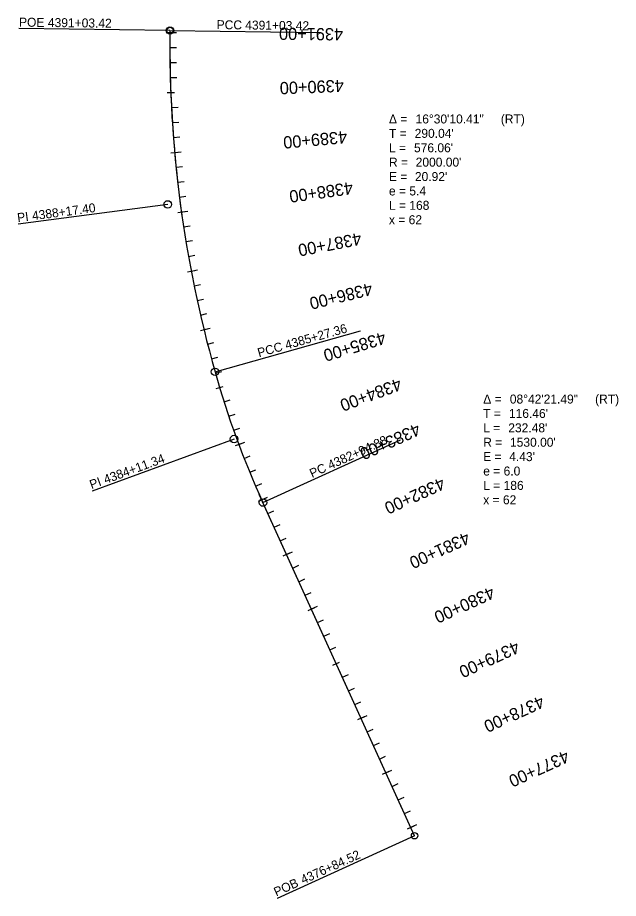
# Model space of a CAD drawing. Extents: x 20506513 to 20507516, y 7970457 to 7971925.
import ezdxf

# ---------------------------------------------------------------- set-up
doc = ezdxf.new("R2010")
doc.units = 0
for name, color, linetype in [('Alignment', 7, 'Continuous'), ('TextAlignment', 7, 'Continuous'), ('TextAlignmentLrg', 7, 'Continuous'), ('TextAlignmentSml', 7, 'Continuous')]:
    doc.layers.add(name, color=color, linetype=linetype)

msp = doc.modelspace()

# ---------------------------------------------------------------- linework, layer by layer
at = {"layer": 'Alignment'}
for q in [(20506916.7, 7971130), (20506922.8, 7971116.7)]:
    msp.add_line((20507175.7, 7970561.2), q, dxfattribs=at)
for centre, radius, start, end in [((20508767.4, 7971878.7), 2000, 179.2791, 188.1288), ((20508767.4, 7971878.7), 2000, 179.2791, 195.782), ((20508315.1, 7971750.8), 1530, 195.782, 204.4879), ((20508315.1, 7971750.8), 1530, 195.782, 204.4879)]:
    msp.add_arc(centre, radius, start, end, dxfattribs=at)
at = {"layer": 'TextAlignment'}
for p, q in [((20506767.6, 7971903.8), (20506515.6, 7971907)), ((20506515.6, 7971907), (20506515.6, 7971907)), ((20506767.6, 7971903.8), (20507019.5, 7971900.7)), ((20507019.5, 7971900.7), (20507019.5, 7971900.7)), ((20506763.9, 7971613.8), (20506514.1, 7971580.8)), ((20506514.1, 7971580.8), (20506514.1, 7971580.8)), ((20506842.8, 7971334.7), (20507085.3, 7971403.3)), ((20506842.8, 7971334.7), (20507085.3, 7971403.3)), ((20507085.3, 7971403.3), (20507085.3, 7971403.3)), ((20507085.3, 7971403.3), (20507085.3, 7971403.3)), ((20506874.5, 7971222.6), (20506637.9, 7971135.9)), ((20506922.8, 7971116.7), (20507152.1, 7971221.1)), ((20507152.1, 7971221.1), (20507152.1, 7971221.1)), ((20506637.9, 7971135.9), (20506637.9, 7971135.9)), ((20507175.7, 7970561.2), (20506946.4, 7970456.7)), ((20506946.4, 7970456.7), (20506946.4, 7970456.7))]:
    msp.add_line(p, q, dxfattribs=at)
for centre, radius in [((20506767.6, 7971903.8), 6.24), ((20506767.6, 7971903.8), 5.34), ((20506763.9, 7971613.8), 6.24), ((20506842.8, 7971334.7), 6.24), ((20506842.8, 7971334.7), 6.24), ((20506874.5, 7971222.6), 6.24), ((20506922.8, 7971116.7), 6.24), ((20507175.7, 7970561.2), 5.34)]:
    msp.add_circle(centre, radius, dxfattribs=at)
at = {"layer": 'TextAlignmentLrg'}
for p, q in [((20506767.5, 7971900.4), (20506778.4, 7971900.3)), ((20506762.8, 7971800.2), (20506775.1, 7971800.7)), ((20506775.3, 7971700.6), (20506786.2, 7971701.6)), ((20506786.7, 7971601.3), (20506797.6, 7971602.8)), ((20506803.1, 7971502.7), (20506813.8, 7971504.7)), ((20506824.3, 7971405), (20506834.9, 7971407.5)), ((20506844.6, 7971306.7), (20506856.3, 7971310.2)), ((20506882.5, 7971213.7), (20506892.7, 7971217.6)), ((20506920.6, 7971121.3), (20506930.6, 7971125.8)), ((20506962.1, 7971030.3), (20506972, 7971034.8)), ((20507003.5, 7970939.3), (20507013.5, 7970943.8)), ((20507039.4, 7970845.8), (20507050.6, 7970850.8)), ((20507086.4, 7970757.3), (20507096.4, 7970761.8)), ((20507127.9, 7970666.3), (20507137.8, 7970670.8)), ((20507169.3, 7970575.3), (20507179.3, 7970579.8))]:
    msp.add_line(p, q, dxfattribs=at)
at = {"layer": 'TextAlignmentSml'}
for p, q in [((20506761.4, 7971900.5), (20506773.6, 7971900.3)), ((20506767.4, 7971875.4), (20506778.3, 7971875.4)), ((20506767.6, 7971850.4), (20506778.5, 7971850.6)), ((20506768.1, 7971825.4), (20506779, 7971825.7)), ((20506762.8, 7971800.2), (20506775.1, 7971800.7)), ((20506770.1, 7971775.5), (20506781, 7971776)), ((20506771.5, 7971750.5), (20506782.4, 7971751.2)), ((20506773.3, 7971725.6), (20506784.2, 7971726.4)), ((20506769.3, 7971700.1), (20506781.4, 7971701.2)), ((20506777.7, 7971675.8), (20506788.6, 7971676.9)), ((20506780.4, 7971650.9), (20506791.3, 7971652.2)), ((20506783.4, 7971626.1), (20506794.3, 7971627.5)), ((20506780.7, 7971600.5), (20506792.8, 7971602.2)), ((20506790.4, 7971576.6), (20506801.2, 7971578.2)), ((20506794.3, 7971551.9), (20506805.1, 7971553.7)), ((20506798.5, 7971527.2), (20506809.3, 7971529.2)), ((20506797.1, 7971501.5), (20506809.1, 7971503.8)), ((20506807.9, 7971478.1), (20506818.6, 7971480.3)), ((20506813.1, 7971453.7), (20506823.8, 7971456)), ((20506818.6, 7971429.3), (20506829.2, 7971431.7)), ((20506818.4, 7971403.5), (20506830.3, 7971406.4)), ((20506830.4, 7971380.7), (20506841, 7971383.4)), ((20506836.8, 7971356.5), (20506847.3, 7971359.4)), ((20506843.4, 7971332.4), (20506854, 7971335.4)), ((20506844.6, 7971306.7), (20506856.3, 7971310.2)), ((20506857.9, 7971284.6), (20506868.3, 7971287.9)), ((20506865.7, 7971260.8), (20506876.1, 7971264.3)), ((20506873.9, 7971237.2), (20506884.2, 7971240.9)), ((20506876.8, 7971211.6), (20506888.2, 7971215.9)), ((20506891.5, 7971190.4), (20506901.6, 7971194.4)), ((20506900.8, 7971167.2), (20506910.9, 7971171.4)), ((20506910.5, 7971144.2), (20506920.6, 7971148.5)), ((20506915.1, 7971118.8), (20506926.2, 7971123.8)), ((20506931, 7971098.6), (20506940.9, 7971103.1)), ((20506941.4, 7971075.8), (20506951.3, 7971080.3)), ((20506951.7, 7971053.1), (20506961.7, 7971057.6)), ((20506956.5, 7971027.8), (20506967.7, 7971032.8)), ((20506972.4, 7971007.6), (20506982.4, 7971012.1)), ((20506982.8, 7970984.8), (20506992.7, 7970989.3)), ((20506993.2, 7970962.1), (20507003.1, 7970966.6)), ((20506998, 7970936.8), (20507009.1, 7970941.8)), ((20507013.9, 7970916.5), (20507023.8, 7970921.1)), ((20507024.3, 7970893.8), (20507034.2, 7970898.3)), ((20507034.6, 7970871), (20507044.6, 7970875.6)), ((20507039.4, 7970845.8), (20507050.6, 7970850.8)), ((20507055.3, 7970825.5), (20507065.3, 7970830.1)), ((20507065.7, 7970802.8), (20507075.6, 7970807.3)), ((20507076.1, 7970780), (20507086, 7970784.6)), ((20507080.9, 7970754.8), (20507092, 7970759.8)), ((20507096.8, 7970734.5), (20507106.7, 7970739.1)), ((20507107.2, 7970711.8), (20507117.1, 7970716.3)), ((20507117.5, 7970689), (20507127.5, 7970693.6)), ((20507122.3, 7970663.7), (20507133.5, 7970668.8)), ((20507138.2, 7970643.5), (20507148.2, 7970648.1)), ((20507148.6, 7970620.8), (20507158.5, 7970625.3)), ((20507159, 7970598), (20507168.9, 7970602.6)), ((20507163.8, 7970572.7), (20507174.9, 7970577.8))]:
    msp.add_line(p, q, dxfattribs=at)

# ---------------------------------------------------------------- texts
at = {"layer": 'TextAlignment'}
for s, rotation, p in [('POE ', 359.2791, (20506515.6, 7971910.3)), ('4391+03.42', 359.2791, (20506563.8, 7971909.7)), ('PCC', 359.2791, (20506845.4, 7971906.1)), ('4391+03.42', 359.2791, (20506893.1, 7971905.5)), ('4388+17.40', 7.5305, (20506538.5, 7971587.3)), ('PI ', 7.5305, (20506513.7, 7971584.1)), ('4385+27.36', 15.782, (20506962, 7971371.8)), ('4385+27.36', 15.782, (20506962, 7971371.8)), ('PCC', 15.782, (20506916.1, 7971358.8)), ('PCC', 15.782, (20506916.1, 7971358.8)), ('4382+94.88', 24.4879, (20507035, 7971171.4)), ('4384+11.34', 20.1349, (20506660.2, 7971147.6)), ('PC', 24.4879, (20507004.7, 7971157.6)), ('PI ', 20.1349, (20506636.7, 7971139)), ('4376+84.52', 24.4879, (20506989.9, 7970480.2)), ('POB ', 24.4879, (20506945, 7970459.7))]:
    msp.add_text(s, height=15, rotation=rotation, dxfattribs=at).set_placement(p)
for s, p in [('Δ = ', (20507133, 7971748.8)), ('16°30\'10.41"', (20507177.4, 7971748.8)), (' (RT)', (20507314.1, 7971748.8)), ('T = ', (20507133, 7971724.8)), ("290.04'", (20507175.9, 7971724.8)), ('L = ', (20507133, 7971700.8)), ("576.06'", (20507174.8, 7971700.8)), ('R = ', (20507133, 7971676.8)), ("2000.00'", (20507177.6, 7971676.8)), ('E = ', (20507133, 7971652.8)), ("20.92'", (20507176.3, 7971652.8)), ('e = 5.4', (20507133, 7971628.8)), ('L = 168', (20507133, 7971604.8)), ('x = 62', (20507133, 7971580.8)), ('Δ = ', (20507290.3, 7971281.8)), ('08°42\'21.49"', (20507334.7, 7971281.8)), (' (RT)', (20507471.4, 7971281.8)), ('T = ', (20507290.3, 7971257.8)), ("116.46'", (20507333.2, 7971257.8)), ('L = ', (20507290.3, 7971233.8)), ("232.48'", (20507332.1, 7971233.8)), ('R = ', (20507290.3, 7971209.8)), ("1530.00'", (20507335, 7971209.8)), ('E = ', (20507290.3, 7971185.8)), ("4.43'", (20507333.7, 7971185.8)), ('e = 6.0', (20507290.3, 7971161.8)), ('L = 186', (20507290.3, 7971137.8)), ('x = 62', (20507290.3, 7971113.8))]:
    msp.add_text(s, height=15, dxfattribs=at).set_placement(p)
at = {"layer": 'TextAlignmentLrg'}
for s, rotation, p in [('4390+00', 182.2418, (20507057.3, 7971821.9)), ('4385+00', 196.8066, (20507124.2, 7971401.8)), ('4380+00', 204.4879, (20507303.7, 7970977.4))]:
    msp.add_text(s, height=20.4, rotation=rotation, dxfattribs=at).set_placement(p)
at = {"layer": 'TextAlignmentSml'}
for s, rotation, p in [('4391+00', 179.377, (20507056.6, 7971907.5)), ('4390+00', 182.2418, (20507057.3, 7971821.9)), ('4389+00', 185.1066, (20507062.3, 7971736.5)), ('4388+00', 187.9714, (20507071.5, 7971651.5)), ('4387+00', 190.8362, (20507085, 7971567)), ('4386+00', 193.701, (20507102.7, 7971483.3)), ('4385+00', 196.8066, (20507124.2, 7971401.8)), ('4384+00', 200.5514, (20507149.5, 7971324.7)), ('4383+00', 204.2962, (20507179.8, 7971249.5)), ('4382+00', 204.4879, (20507220.8, 7971159.4)), ('4381+00', 204.4879, (20507262.3, 7971068.4)), ('4380+00', 204.4879, (20507303.7, 7970977.4)), ('4379+00', 204.4879, (20507345.2, 7970886.4)), ('4378+00', 204.4879, (20507386.6, 7970795.4)), ('4377+00', 204.4879, (20507428.1, 7970704.3))]:
    msp.add_text(s, height=20.4, rotation=rotation, dxfattribs=at).set_placement(p)

doc.saveas('drawing.dxf')
